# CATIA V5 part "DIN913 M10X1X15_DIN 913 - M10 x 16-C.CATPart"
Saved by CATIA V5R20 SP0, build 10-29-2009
Part number: DIN913 M10X1X15_DIN 913 - M10 x 16-C
Revision: ANY
Definition: UNKNOWN
Nomenclature: DIN913 M10X1X15_DIN 913 - M10 x 16-C
Source: Unknown
Bounding box of the stored display mesh (mm): x 0 to 15, y -5 to 5, z -5 to 5
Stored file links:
  C:\Users\Utente\Desktop\IO LAVORO\3D X SITO CF\CUMSA\3D files CG\CG 604035\DIN913 M10X1X15_DIN 913 - M10 x 16-C.CATPart
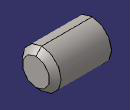
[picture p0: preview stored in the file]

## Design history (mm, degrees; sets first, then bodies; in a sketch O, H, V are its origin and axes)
Body1 "Hex" (main body)
  Solid1: solid without history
